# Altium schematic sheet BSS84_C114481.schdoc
size 127 x 101 mm
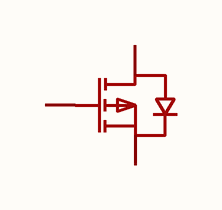
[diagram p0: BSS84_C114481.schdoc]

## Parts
Q?  bss84_c114481  [SOT-23-3_L2.9-W1.6-P1.90-LS2.8-BR]  (value not drawn)

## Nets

Not connected (* = marked no-connect by the designer): Q? 1(G) 2(S) 3(D)

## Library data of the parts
Q? = bss84_c114481: 数量:1个P沟道;漏源电压(Vdss):50V;连续漏极电流(Id):130mA;导通电阻(RDS(on)):4.5Ω@10V;耗散功率(Pd):225mW;阈值电压(Vgs(th)):2V;; Manufacturer: CJ(江苏长电/长晶); ManufacturerPart: BSS84; AddInBom: yes; ModelId: 89cb27a44ab2466697082bb9fd73a7d0; ModelName: SOT-23-3L_L2.9-W1.6-H1.1-LS2.8-P0.95; ModelTransform: 114.173,110.236,0,90,0,0,0,0,0; Number: 1个P沟道; Drain to Source Voltage: 50V; Current - Continuous Drain(Id): 130mA; Pd - Power Dissipation: 225mW; Gate Threshold Voltage (Vgs(th)): 2V; Input Capacitance(Ciss): 30pF; Reverse Transfer Capacitance (Crss@Vds): 5pF; Type: P沟道; Output Capacitance(Coss): 10pF; Vgs: ±20V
